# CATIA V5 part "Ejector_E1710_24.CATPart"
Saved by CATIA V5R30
Part number: Vyhazovac_7x160_1
Nomenclature: E1710/7x160
Description: MEUSBURGER
Property "Material": "1.221"
Publications: "__DrillHole", "Base"
Bounding box of the stored display mesh (mm): x -5.992 to 5.992, y -5.992 to 5.992, z 0 to 152
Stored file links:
  E:\Bakalarka\Model\Forma_v7\Ejector_E1710_24.CATPart
  E:\dev\MoldDesign\intel_a\startup\components\MoldCatalog\Ejector\Meusburger\Ejector_E1710\TableE1710.txt
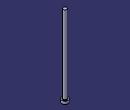
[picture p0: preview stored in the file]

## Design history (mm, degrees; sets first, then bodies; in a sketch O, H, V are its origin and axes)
Parameters
  Ref = "E1710/7x160" {design table}
  D1 = 7 mm {design table}
  D3 = 12 mm {design table}
  L = 160 mm {design table}
  L3 = 5 mm {design table}
  R = 0.5 mm {design table}
  k_d3 = 13 mm {design table}
  k_d1 = 7.2 mm {design table}
  k_F = 0.5 mm {design table}
  kl = 17 mm {design table}
  Mat = "1.221" {design table}
  HeatTreat = "ISO6751" {design table}
  Offset_Parting = 10 mm
  Anti_Rotation = "Normal"
  Anti_Rotation_D = 4 mm
  Anti_Rotation_D_Icut = 4 mm
  Add_Length_L = 1.3377 mm
  Add_Length_D3 = 0 mm
  SupplierRef = "Meusburger 2017"
  BmpRef = "F_MldEjectorD1"
  DrillHole_Length = 225 mm
  ValidationTest = false
  Anti_Rotation_D_min = 4 mm {= OffSet_D1 /2}
  Anti_Rotation_D_max = 5.925 mm {= D3/2-0.075mm}
  Anti_Rotation_D_ref = 4 mm {= Anti_Rotation_D}
  Anti_Rotation_D_Icut_ref = 4 mm {= Anti_Rotation_D_Icut}
  Anti_Rotation_Ref_Icut = 2.3246 mm
  Offset_L = 20 mm
  D = 7 mm {= D1}
  OffSet_D1 = 8 mm {= D1+2*R}
  OffSet_D3 = 13 mm {= D3+1mm}
  XG_Split = -108 mm
  YG_Split = 20 mm
  ZG_Split = -198 mm
  DirX_Split = 0 mm
  DirY_Split = 0 mm
  DirZ_Split = 1 mm
Set1 "BaseBody"
  Point1 "Base": (0, 0, 0)
  Plane1: type Offset, RefPlane xy-plane, Offset 225 {= DrillHole_Length}, reversed
  Sketch1 "Sketch.2" on xy-plane, origin (0, 0, 0), H (1, 0, 0), V (0, 1, 0)
    point P1 (-0.46, 1.1623)
    point P2 (0.46, 1.1623)
    construction line L1 (-0.46, 1.1623) -> (0.46, 1.1623)
    point P3 (0.46, -1.1623)
    line L2 (0.46, -1.1623) -> (0.46, 1.1623)
    point P4 (-0.46, -1.1623)
    construction line L3 (0.46, -1.1623) -> (-0.46, -1.1623)
    line L4 (-0.46, 1.1623) -> (-0.46, -1.1623)
    point P5 (-0.21, 1.1623)
    arc A1 centre (-0.21, 1.1623) radius 0.25 from (-0.21, 1.4123) to (-0.46, 1.1623) ccw
    point P7 (0.21, 1.1623)
    point P8 (0.21, 1.4123)
    arc A2 centre (0.21, 1.1623) radius 0.25 from (0.46, 1.1623) to (0.21, 1.4123) ccw
    line L5 (-0.21, 1.4123) -> (0.21, 1.4123)
    point P9 (-0.46, -1.1623)
    arc A3 centre (-0.21, -1.1623) radius 0.25 from (-0.46, -1.1623) to (-0.21, -1.4123) ccw
    point P11 (0.21, -1.4123)
    line L6 (-0.21, -1.4123) -> (0.21, -1.4123)
    point P12 (0.46, -1.1623)
    arc A4 centre (0.21, -1.1623) radius 0.25 from (0.21, -1.4123) to (0.46, -1.1623) ccw
    point P14 (-0.46, 1.1623)
    point P15 (-0.46, -1.1623)
    point P16 (0.46, 1.1623)
    point P17 (0.46, -1.1623)
    reference projected circle E1 centre (0, 0) radius 1.25 from edge [face of Shaft1 from Sketch2.L3 | face of Shaft1 from Sketch2.L4]
    reference projected circle E2 centre (0, 0) radius 1.25 from edge [face of Shaft1 from Sketch2.L3 | face of Shaft1 from Sketch2.L4]
    reference projected circle E3 centre (0, 0) radius 1.25 from edge [face of Shaft1 from Sketch2.L3 | face of Shaft1 from Sketch2.L4]
    reference projected circle E4 centre (0, 0) radius 1.25 from edge [face of Shaft1 from Sketch2.L3 | face of Shaft1 from Sketch2.L4]
    point P18 (-0.46, -1.1623)
    point P19 (-0.21, -1.4123)
    point P20 (0.21, -1.4123)
    point P21 (0.46, -1.1623)
    point P22 (-0.21, -1.4123)
    point P23 (0.21, -1.4123)
    distance P14 P15 = 2.3246 (reference)
    distance P16 P17 = 2.3246 (reference)
    distance L1 P14 = 0 (reference)
    radius A1 = 3.5
    distance L4 V = 4.01
    distance L2 V = 5.935
    distance L5 L6 = 12
    horizontal: L1 H, L3 H, L5 H
    vertical: L2 V, L4 V
    coincidence: P5 L1, P7 L1, P3 P12, P14 L4, P15 L4, P16 L2, P17 L2, P14 E1, P15 E2, P16 E3, P17 E4, P3 P21, P4 P18, P20 P23, P19 P22
    tangency: A1 L4, A2 L2, A2 L5, A1 L5
    symmetry: P1 P9 H, A1 A3 H, P8 P11 H, L5 L6 H, P2 P12 H, A2 A4 H
  DatumSurface1
Body1 "PartBody" (main body)
  Sketch2 "Sketch.1" on zx-plane, origin (0, 0, 0), H (-1, 0, 0), V (0, 0, 1)
    point P1 (0, 160)
    line L1 (3.5, 160) -> (0, 160)
    line L2 (3.5, 5) -> (3.5, 160)
    line L3 (6, 5) -> (3.5, 5)
    line L4 (6, 0) -> (6, 5)
    point P5 (0, 0)
    line L5 (0, 0) -> (6, 0)
    point P6 (0, 160)
    axis line L6 (0, 160) -> (0, 0)
    point P7 (0, 0)
    point P8 (3.5, 5)
    point P9 (3.5, 5)
    line L7 (0, 160) -> (0, 0)
    distance L5 L3 = 5 {= L3}
    distance L5 L1 = 160 {= L}
    distance L2 L6 = 3.5 {= D1 /2}
    distance L4 L6 = 6 {= D3 /2}
    coincidence: L6 P5, P1 L6, L5 H, L6 V, P7 O, P6 P1, P8 P9
    vertical: L2 V, L7 V
    horizontal: L1 H
  Shaft1 "Shaft.1": profile Sketch2, axis Sketch2.L6, angle 360
  Pocket1 "Pocket.1": profile Sketch1, direction (0, 0, 1), length 6, outer side, deactivated
  Pocket2 "Pocket.2": profile Sketch1, direction (0, 0, 1), length 6, outer side, deactivated
  Fillet1: radius 0.5 {= R}, on edge [face of Shaft1 from Sketch2.L2 | face of Shaft1 from Sketch2.L3]
  Pocket3: profile face of Shaft1 from Sketch2.L1, direction along axis of face of Shaft1 from Sketch2.L2, up to face of DatumSurface1
Body2 "__DrillHole"
  Sketch3 "Sketch.3" on face of Shaft1, origin (0, 0, 0), H (1, 0, 0), V (0, -1, 0)
    point P1 (0, 0)
    reference projected point E1 (0, 0) from Point1
    coincidence: E1 P1
  Hole1 "Hole.1": placed by Sketch3, at (0, 0, 0) direction (0, 0, 1), diameter 8 {= OffSet_D1}, depth 140 {= L-Offset_L}
  Sketch4 "Sketch.4" on face of Shaft1, origin (0, 0, 0), H (1, 0, 0), V (0, -1, 0)
    point P1 (0, 0)
    reference projected point E1 (0, 0) from Point1
    coincidence: E1 P1
  Hole2 "Hole.2": placed by Sketch4, at (0, 0, 0) direction (0, 0, 1), diameter 7 {= D1}, depth 160 {= L}
  Sketch5 "Sketch.5" on face of Shaft1 from Sketch2.L3, origin (0, 0, 5), H (1, 0, 0), V (0, 1, 0)
    point P1 (0, 0)
    reference projected point E1 (0, 0) from Point1
    coincidence: E1 P1
  Hole3 "Hole.3": placed by Sketch5, at (0, 0, 5) direction (0, 0, -1), diameter 13 {= OffSet_D3}, depth 230 {= L3 +DrillHole_Length}
  Chamfer1: length 0.5 {= k_F}, angle 45, on edge [face of Hole1 | face of Hole3]
  Body3 "__Body.1"
    Pocket4 "Pocket.3": profile Sketch1, direction (0, 0, -1), length 225, opposite side length 5, deactivated
  Assemble1: tool Body3
  Chamfer2: length 0.5 {= k_F}, angle 45, on edge [start face of Pocket4 | face of Hole1], deactivated
  Body4 "__Body.2"
    Pocket5 "Pocket.4": profile Sketch1, direction (0, 0, -1), length 225, opposite side length 5, deactivated
  Assemble2: tool Body4
  Chamfer3: length 0.5 {= k_F}, angle 45, on edge [start face of Pocket5 | face of Hole1], deactivated
Relations
  design table "TableE1710", configuration 278, drives Ref, D1, D3, L, L3, R, k_d3, k_d1, k_F, kl, Mat, HeatTreat
  Offset_L = 20mm (deactivated)
  rule "Cut_Head_rule":
    let sketch_cut (length)
    let PartBody_Pocket_Sketch (Boolean)
    let I_PartBody_Pocket (Boolean)
    let D_PartBody_Pocket (Boolean)
    let N_DrillHole_Hole (Boolean)
    let N_DrillHole_Hole_Sketch (Boolean)
    let I_DrillHole_Pocket (Boolean)
    let D_DrillHole_Pocket (Boolean)
    /* --------------------------------------------------------------------------------------*/
    if Anti_Rotation =="Normal"
    {
    	sketch_cut=Anti_Rotation_D_max
    	PartBody_Pocket_Sketch = false
    	I_PartBody_Pocket = false
    	D_PartBody_Pocket = false
    	N_DrillHole_Hole = true
    	N_DrillHole_Hole_Sketch = true
    	I_DrillHole_Pocket = false
    	D_DrillHole_Pocket = false
    	Chamfer1.Activity= true
    	Chamfer2.Activity= false
    	Chamfer3.Activity= false
    }
    if Anti_Rotation == "I_Cut"
    {
    	sketch_cut=Anti_Rotation_D_Icut_ref
    	PartBody_Pocket_Sketch = true
    	I_PartBody_Pocket = true
    	D_PartBody_Pocket = false
    	N_DrillHole_Hole = false
    	N_DrillHole_Hole_Sketch = false
    	I_DrillHole_Pocket = true
    	D_DrillHole_Pocket = false
    	Chamfer1.Activity= false
    	Chamfer2.Activity= true
    	Chamfer3.Activity= false
    }
    if Anti_Rotation =="D_Cut"
    {
    	sketch_cut=Anti_Rotation_D_max
    	PartBody_Pocket_Sketch = true
    	I_PartBody_Pocket = false
    	D_PartBody_Pocket = true
    	N_DrillHole_Hole = false
    	N_DrillHole_Hole_Sketch = false
    	I_DrillHole_Pocket = false
    	D_DrillHole_Pocket = true
    	Chamfer1.Activity= false
    	Chamfer2.Activity= false
    	Chamfer3.Activity= true
    }
    /* --------------------------------------------------------------------------------------*/
    Sketch1.distance(L2 V) = sketch_cut+0.01mm
    Sketch1.distance(L4 V) =Anti_Rotation_D_ref+0.01mm
    Sketch1.radius(A1) =D/2
    Pocket4.FirstLimit.Depth = DrillHole_Length
    Pocket5.FirstLimit.Depth = DrillHole_Length
    Pocket1.FirstLimit.Depth = L3+1mm
    Pocket2.FirstLimit.Depth = L3+1mm
    Pocket4.SecondLimit.Depth = L3
    Pocket5.SecondLimit.Depth =L3
    Pocket1.Activity = I_PartBody_Pocket
    Pocket2.Activity = D_PartBody_Pocket
    Sketch1.Activity =PartBody_Pocket_Sketch
    Hole3.Activity= N_DrillHole_Hole
    Sketch5.Activity = N_DrillHole_Hole_Sketch
    Pocket4.Activity = I_DrillHole_Pocket
    Pocket5.Activity  = D_DrillHole_Pocket
  rule "Anti_Rotation_Icut_constrain":
    let Ref1(length)
    let Ref2(length)
    let Ref3(length)
    let Diam1(length)
    let Diam2(length)
    let Add_Length_Lmin (length)
    Ref1=Sketch1.distance(P14 P15)
    Ref2=Sketch1.distance(P16 P17)
    Diam1=D
    Diam2=D3
    /* --------------------------------------------------------------------*/
    if Ref1 >Ref2
    	Anti_Rotation_Ref_Icut = Ref1
    else
    	Anti_Rotation_Ref_Icut  =Ref2
    Add_Length_D3 .InferiorRange=Anti_Rotation_Ref_Icut /2+Diam1/2 -Diam2/2
    if Add_Length_D3 .InferiorRange<0mm
    	Add_Length_D3 .InferiorRange=0mm
    if ValidationTest == "true"
    	Ref3   = 2*Add_Length_L +Anti_Rotation_Ref_Icut  +2*Diam1/2
    else
    	Ref3  =Diam2+2*Add_Length_D3
    if Ref3 <Diam2
    {
    	Ref3 =Diam2
    }
    /* --------------------------------------------------------------------*/
    Sketch1.distance(L5 L6) = Ref3
    Add_Length_L .InferiorRange=Diam2/2-Anti_Rotation_Ref_Icut/2-Diam1/2
    Add_Length_Lmin=Diam2/2-Anti_Rotation_Ref_Icut/2-Diam1/2
    if Add_Length_Lmin<0mm
    	Add_Length_L .InferiorRange=0mm
    else
    	Add_Length_L .InferiorRange=Add_Length_Lmin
